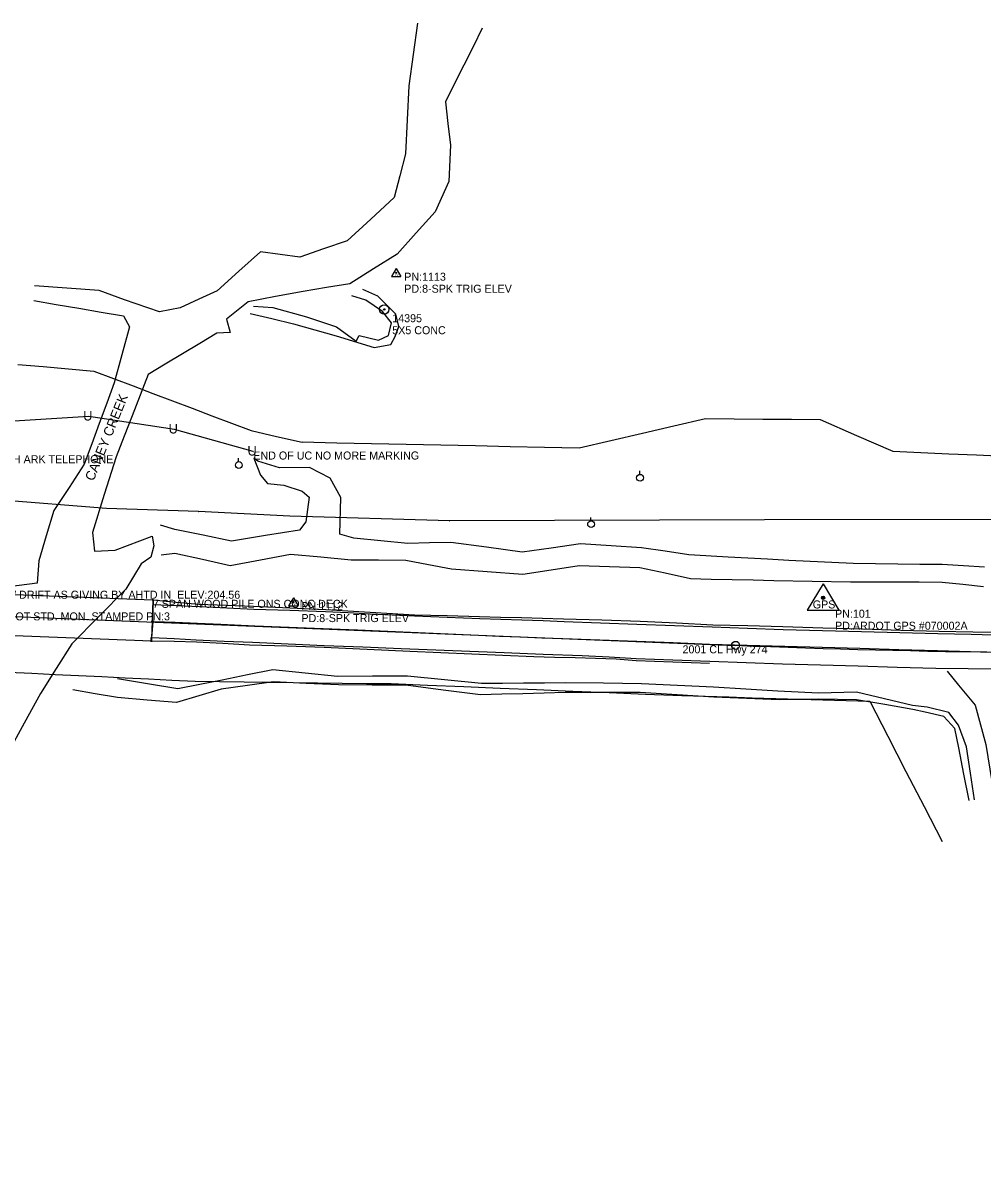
# Model space of a CAD drawing. Extents: x 1138803 to 1169983, y 1655906 to 1658226.
# Drawn here: x 1141577 to 1142177, y 1657286 to 1658006 of the extents above; entities that cross this region are included whole.
import ezdxf

# ---------------------------------------------------------------- set-up
doc = ezdxf.new("R2010")
doc.units = 0
for name, color, linetype in [('Default', 7, 'Continuous'), ('R_Annotation', 7, 'Continuous'), ('S_BRIDGE', 7, 'Continuous'), ('S_BRIDGE_ANNOT', 7, 'Continuous'), ('S_DITCHLINE', 7, 'Continuous'), ('S_EDGE_PAVEMENT', 7, 'Continuous'), ('S_EXISTING_ALIGNMENT', 7, 'Continuous'), ('S_EXISTING_ALIGNMENT_ANNOT', 7, 'Continuous'), ('S_FIBER_OPTIC_CABLE', 7, 'Continuous'), ('S_GRAVEL_ROAD', 7, 'Continuous'), ('S_HIST_HIGH_WATER_ANNOT', 7, 'Continuous'), ('S_IRON_PIN', 7, 'Continuous'), ('S_IRON_PIN_ANNOT', 7, 'Continuous'), ('S_MSC_PT_SYM', 7, 'Continuous'), ('S_PAVEMENT_CROWN', 7, 'Continuous'), ('S_PRIMARY_CTL', 7, 'Continuous'), ('S_PRIMARY_CTL_ANNOT', 7, 'Continuous'), ('S_SECONDARY_CTL', 7, 'Continuous'), ('S_SECONDARY_CTL_ANNOT', 7, 'Continuous'), ('S_SHOULDER', 7, 'Continuous'), ('S_STR_PT_SYM', 7, 'Continuous'), ('S_STREAM', 7, 'Continuous'), ('S_SURVEY_TEXT_ANNOT', 7, 'Continuous'), ('S_TREE', 7, 'Continuous'), ('S_UNDERGROUND_CABLE', 7, 'Continuous'), ('S_UTILITY_POLE', 7, 'Continuous'), ('S_UTILITY_POLE_ANNOT', 7, 'Continuous'), ('S_UTL_PT_SYM', 7, 'Continuous')]:
    doc.layers.add(name, color=color, linetype=linetype)

msp = doc.modelspace()

# ---------------------------------------------------------------- linework, layer by layer
at = {"layer": 'S_BRIDGE'}
for p, q in [((1141551.33, 1657650), (1141657.88, 1657645.9)), ((1141657.88, 1657645.9), (1141657.41, 1657632.31)), ((1141657.41, 1657632.31), (1141657.03, 1657621.9)), ((1141656.97, 1657620.11), (1141550.22, 1657624.21)), ((1141657.03, 1657621.9), (1141656.97, 1657620.63)), ((1141656.97, 1657620.63), (1141656.97, 1657620.11))]:
    msp.add_line(p, q, dxfattribs=at)
at = {"layer": 'S_DITCHLINE'}
for points in [[(1141718.73, 1657824.92), (1141732.27, 1657821.68), (1141745.82, 1657818.45), (1141759.11, 1657814.62), (1141772.41, 1657810.79), (1141796.27, 1657803.51), (1141806.65, 1657805.46), (1141809.29, 1657810.45), (1141811.59, 1657816.7), (1141809.83, 1657824.33), (1141798.52, 1657835.69), (1141789.15, 1657839.79)], [(1141720.76, 1657829.49), (1141732.83, 1657828.69), (1141753.89, 1657822.77), (1141772.79, 1657816.6), (1141785.06, 1657807.64), (1141786.87, 1657811), (1141798.88, 1657808.17), (1141805.12, 1657811.02), (1141807.13, 1657819.04), (1141801.49, 1657826), (1141791.13, 1657833.23), (1141782.24, 1657835.81)], [(1142177.83, 1657666.32), (1142164.58, 1657667.1), (1142151.33, 1657667.88), (1142137.42, 1657668.06), (1142123.51, 1657668.23), (1142109.6, 1657668.41), (1142095.69, 1657668.58), (1142082.27, 1657669.25), (1142068.85, 1657669.91), (1142055.43, 1657670.58), (1142042.01, 1657671.25), (1142017.45, 1657672.62), (1141992.89, 1657674), (1141978.17, 1657676.24), (1141963.44, 1657678.48), (1141944.33, 1657679.64), (1141925.21, 1657680.8), (1141906.97, 1657678.25), (1141888.73, 1657675.7), (1141866.46, 1657678.76), (1141844.19, 1657681.82), (1141830.78, 1657681.42), (1141817.37, 1657681.01), (1141800.49, 1657682.7), (1141783.6, 1657684.39), (1141774.69, 1657686.95), (1141775.46, 1657709.79), (1141768.71, 1657721.9), (1141755.78, 1657728.68), (1141736.99, 1657728.43), (1141723.49, 1657732.46), (1141720.94, 1657734.45), (1141725.21, 1657723.84), (1141729.47, 1657718.63), (1141739.76, 1657717.51), (1141751.29, 1657713.78), (1141755.64, 1657710.14), (1141753.6, 1657694.74), (1141749.5, 1657689.52), (1141728.24, 1657686.09), (1141706.98, 1657682.65), (1141689.27, 1657686.27), (1141671.56, 1657689.88), (1141662.65, 1657692.57)], [(1142177.17, 1657654.11), (1142164.22, 1657655.46), (1142151.28, 1657656.8), (1142136.97, 1657656.84), (1142122.67, 1657656.88), (1142108.36, 1657656.92), (1142094.06, 1657656.96), (1142070.1, 1657657.39), (1142046.13, 1657657.82), (1142033.08, 1657658.11), (1142020.02, 1657658.41), (1142006.97, 1657658.7), (1141993.91, 1657658.99), (1141978.12, 1657662.47), (1141962.33, 1657665.95), (1141943.39, 1657666.54), (1141924.45, 1657667.12), (1141906.79, 1657664.47), (1141889.13, 1657661.81), (1141866.8, 1657663.47), (1141844.48, 1657665.12), (1141830.26, 1657667.79), (1141816.05, 1657670.45), (1141798.95, 1657670.59), (1141781.86, 1657670.73), (1141762.92, 1657672.51), (1141743.97, 1657674.28), (1141725.14, 1657670.76), (1141706.31, 1657667.23), (1141689, 1657671.08), (1141671.69, 1657674.92), (1141663.08, 1657673.89)], [(1142171.5, 1657520.96), (1142168.99, 1657537.47), (1142166.49, 1657553.97), (1142161.57, 1657567.57), (1142155.52, 1657575.4), (1142141.81, 1657578.88), (1142132.82, 1657579.84), (1142115.26, 1657583.98), (1142097.69, 1657588.13), (1142073.89, 1657587.54), (1142061.28, 1657588.23), (1142048.67, 1657588.92), (1142028.51, 1657590.13), (1142008.34, 1657591.35), (1141985.83, 1657592.39), (1141963.32, 1657593.43), (1141939.61, 1657593.73), (1141915.9, 1657594.03), (1141902.76, 1657593.91), (1141889.62, 1657593.8), (1141876.47, 1657593.68), (1141863.33, 1657593.56), (1141840.19, 1657595.91), (1141817.05, 1657598.26), (1141795.21, 1657598.09), (1141773.37, 1657597.92), (1141753.13, 1657600.06), (1141732.88, 1657602.21), (1141717.09, 1657598.98), (1141701.29, 1657595.75), (1141687.36, 1657592.98), (1141673.42, 1657590.21), (1141654.59, 1657593.37), (1141635.77, 1657596.52)], [(1142168.11, 1657520.52), (1142164.89, 1657536.95), (1142161.67, 1657553.39), (1142159.15, 1657565.53), (1142152.34, 1657572.92), (1142140.61, 1657575.66), (1142132.92, 1657577.41), (1142115.38, 1657580.44), (1142097.83, 1657583.47), (1142074.06, 1657583.86), (1142049.31, 1657583.38), (1142028.92, 1657584.24), (1142008.53, 1657585.1), (1141985.56, 1657586.55), (1141962.6, 1657588), (1141939.13, 1657587.94), (1141915.67, 1657587.89), (1141902.43, 1657587.54), (1141889.19, 1657587.19), (1141875.95, 1657586.84), (1141862.71, 1657586.49), (1141839.36, 1657589.51), (1141816, 1657592.53), (1141795, 1657592.65), (1141773.99, 1657592.76), (1141753.67, 1657593.66), (1141733.35, 1657594.55), (1141716.97, 1657592.34), (1141700.6, 1657590.13), (1141686.66, 1657585.93), (1141672.71, 1657581.74), (1141654.25, 1657583.28), (1141635.79, 1657584.81), (1141621.8, 1657587.21), (1141607.82, 1657589.6)]]:
    msp.add_lwpolyline(points, dxfattribs=at)
at = {"layer": 'S_EDGE_PAVEMENT'}
for points in [[(1142187.85, 1657602.51), (1142167.59, 1657602.72), (1142147.34, 1657602.93), (1142123.11, 1657603.7), (1142098.88, 1657604.47), (1142075.14, 1657605.03), (1142051.4, 1657605.59), (1142028.68, 1657606.48), (1142005.96, 1657607.37), (1141982.99, 1657608.24), (1141960.03, 1657609.11), (1141943.17, 1657610.03), (1141926.3, 1657610.96), (1141901.89, 1657611.82), (1141877.47, 1657612.67), (1141861.4, 1657613.35), (1141845.34, 1657614.02), (1141829.27, 1657614.69), (1141813.21, 1657615.36), (1141789.14, 1657616.3), (1141765.07, 1657617.24), (1141742.58, 1657618.21), (1141720.09, 1657619.18), (1141702.56, 1657619.95), (1141685.04, 1657620.72), (1141671.17, 1657621.47), (1141657.31, 1657622.22), (1141658.08, 1657632.26), (1141658.07, 1657642.64)], [(1142190.31, 1657623.66), (1142169.41, 1657624.17), (1142148.51, 1657624.68), (1142124.74, 1657625.25), (1142100.96, 1657625.81), (1142076.39, 1657626.48), (1142051.81, 1657627.15), (1142029.68, 1657628.01), (1142007.54, 1657628.87), (1141984.02, 1657629.71), (1141960.5, 1657630.55), (1141937.75, 1657631.38), (1141915.01, 1657632.21), (1141901.81, 1657632.67), (1141888.61, 1657633.12), (1141875.4, 1657633.57), (1141862.2, 1657634.03), (1141841.78, 1657634.85), (1141821.37, 1657635.67), (1141807.51, 1657636.35), (1141793.65, 1657637.03), (1141779.78, 1657637.71), (1141765.92, 1657638.39), (1141743.52, 1657639.14), (1141721.11, 1657639.88), (1141704.1, 1657640.74), (1141687.08, 1657641.6), (1141672.61, 1657642.22), (1141658.14, 1657642.84)]]:
    msp.add_lwpolyline(points, dxfattribs=at)
at = {"layer": 'S_EXISTING_ALIGNMENT'}
msp.add_line((1140481.53, 1657679.14), (1142022.15, 1657617.46), dxfattribs=at)
msp.add_circle((1142022.15, 1657617.46), 2.5, dxfattribs=at)
msp.add_arc((1142252.26, 1663365.55), 5752.69, 267.707455, 274.678683, dxfattribs=at)
at = {"layer": 'S_FIBER_OPTIC_CABLE'}
for p, q in [((1141628.93, 1657703.02), (1141522.77, 1657711.39)), ((1141686.36, 1657701.07), (1141628.93, 1657703.02)), ((1141743.49, 1657698.2), (1141686.36, 1657701.07)), ((1141843.42, 1657695.23), (1141743.49, 1657698.2)), ((1142040.24, 1657695.96), (1141843.42, 1657695.23)), ((1142205.85, 1657696.12), (1142040.24, 1657695.96))]:
    msp.add_line(p, q, dxfattribs=at)
at = {"layer": 'S_GRAVEL_ROAD'}
msp.add_lwpolyline([(1142154.33, 1657601.26), (1142161.44, 1657592.63), (1142171.83, 1657580.17), (1142175.18, 1657567.86), (1142178.54, 1657555.56), (1142182.38, 1657532.32), (1142183.56, 1657516.44), (1142184.74, 1657500.56), (1142185.59, 1657476.1), (1142186.43, 1657451.65), (1142187.52, 1657429.02), (1142188.61, 1657406.39), (1142189.59, 1657381.64), (1142190.57, 1657356.89), (1142191.64, 1657340.42), (1142192.7, 1657323.94), (1142193.66, 1657304.9), (1142194.61, 1657285.86)], dxfattribs=at)
at = {"layer": 'S_IRON_PIN'}
for radius in [2.91, 0.411, 0.262, 0.212, 0.145, 0.0822, 0.0581]:
    msp.add_circle((1141802.55, 1657827.38), radius, dxfattribs=at)
at = {"layer": 'S_MSC_PT_SYM'}
msp.add_lwpolyline([(1141720.7, 1657738.58), (1141720.7, 1657738.63), (1141720.7, 1657738.58), (1141720.65, 1657738.58), (1141720.7, 1657738.58), (1141720.7, 1657738.53), (1141720.7, 1657738.58), (1141720.75, 1657738.58)], dxfattribs=at)
at = {"layer": 'S_PAVEMENT_CROWN'}
msp.add_lwpolyline([(1142189.52, 1657612.97), (1142168.97, 1657613.5), (1142148.43, 1657614.03), (1142124.12, 1657614.72), (1142099.8, 1657615.41), (1142076.36, 1657616.05), (1142052.91, 1657616.7), (1142029.37, 1657617.39), (1142005.84, 1657618.08), (1141983.08, 1657619), (1141960.33, 1657619.91), (1141937.21, 1657620.71), (1141914.09, 1657621.5), (1141900.95, 1657622.02), (1141887.8, 1657622.53), (1141874.66, 1657623.05), (1141861.52, 1657623.57), (1141842.59, 1657624.42), (1141823.67, 1657625.27), (1141804.75, 1657626.11), (1141785.82, 1657626.96), (1141764.46, 1657627.82), (1141743.09, 1657628.67), (1141721.72, 1657629.53), (1141700.36, 1657630.38), (1141685.79, 1657631.1), (1141671.95, 1657631.68), (1141658.51, 1657632.24)], dxfattribs=at)
at = {"layer": 'S_PRIMARY_CTL'}
for p, q in [((1142076.83, 1657655.92), (1142066.8, 1657639.41)), ((1142076.83, 1657655.92), (1142086.66, 1657639.41)), ((1142066.8, 1657639.41), (1142086.66, 1657639.41))]:
    msp.add_line(p, q, dxfattribs=at)
for radius in [1.04, 0.609, 0.344]:
    msp.add_circle((1142076.83, 1657647.22), radius, dxfattribs=at)
at = {"layer": 'S_SECONDARY_CTL'}
for p, q in [((1141810.06, 1657852.93), (1141807.05, 1657847.97)), ((1141810.06, 1657852.93), (1141813.01, 1657847.97)), ((1141807.05, 1657847.97), (1141813.01, 1657847.97)), ((1141745.76, 1657647.09), (1141742.75, 1657642.14)), ((1141745.76, 1657647.09), (1141748.7, 1657642.14)), ((1141742.75, 1657642.14), (1141748.7, 1657642.14))]:
    msp.add_line(p, q, dxfattribs=at)
for centre, radius in [((1141810.06, 1657850.32), 0.311), ((1141810.06, 1657850.32), 0.183), ((1141810.06, 1657850.32), 0.103), ((1141745.76, 1657644.48), 0.311), ((1141745.76, 1657644.48), 0.183), ((1141745.76, 1657644.48), 0.103)]:
    msp.add_circle(centre, radius, dxfattribs=at)
at = {"layer": 'S_SHOULDER'}
for points in [[(1142191.33, 1657625.49), (1142170.42, 1657625.78), (1142149.51, 1657626.06), (1142125.5, 1657626.83), (1142101.49, 1657627.61), (1142076.6, 1657628.28), (1142051.71, 1657628.96), (1142029.83, 1657629.55), (1142007.95, 1657630.14), (1141985.22, 1657631.26), (1141962.48, 1657632.38), (1141938.57, 1657633.11), (1141914.67, 1657633.84), (1141901.51, 1657634.21), (1141888.35, 1657634.57), (1141875.19, 1657634.93), (1141862.04, 1657635.3), (1141841.79, 1657635.84), (1141821.55, 1657636.37), (1141807.66, 1657637.19), (1141793.77, 1657638.02), (1141779.88, 1657638.84), (1141765.99, 1657639.66), (1141743.44, 1657640.71), (1141720.89, 1657641.76), (1141703.81, 1657642.36), (1141686.73, 1657642.97), (1141672.46, 1657644.32), (1141658.18, 1657645.67), (1141658.17, 1657644.17), (1141658.02, 1657643.09)], [(1142005.8, 1657606.21), (1141982.9, 1657606.96), (1141959.99, 1657607.72), (1141947.52, 1657608.87), (1141934.66, 1657609.23), (1141921.79, 1657609.58), (1141908.92, 1657609.94), (1141896.06, 1657610.3), (1141876.7, 1657611.15), (1141857.34, 1657612), (1141837.99, 1657612.84), (1141818.63, 1657613.69), (1141805.21, 1657614.32), (1141791.78, 1657614.95), (1141778.36, 1657615.58), (1141764.94, 1657616.21), (1141741.61, 1657616.93), (1141718.29, 1657617.66), (1141701.7, 1657618.53), (1141685.12, 1657619.4), (1141671.16, 1657619.76), (1141657.2, 1657620.12), (1141657.22, 1657621.67)]]:
    msp.add_lwpolyline(points, dxfattribs=at)
at = {"layer": 'S_STR_PT_SYM'}
for points in [[(1141657.88, 1657645.9), (1141657.88, 1657646.4), (1141657.88, 1657645.9), (1141657.38, 1657645.9), (1141657.88, 1657645.9), (1141657.88, 1657645.4), (1141657.88, 1657645.9), (1141658.38, 1657645.9)], [(1141657.41, 1657632.31), (1141657.41, 1657632.81), (1141657.41, 1657632.31), (1141656.91, 1657632.31), (1141657.41, 1657632.31), (1141657.41, 1657631.81), (1141657.41, 1657632.31), (1141657.91, 1657632.31)], [(1141657.03, 1657621.9), (1141657.03, 1657622.4), (1141657.03, 1657621.9), (1141656.53, 1657621.9), (1141657.03, 1657621.9), (1141657.03, 1657621.4), (1141657.03, 1657621.9), (1141657.53, 1657621.9)], [(1141656.97, 1657620.63), (1141656.97, 1657621.13), (1141656.97, 1657620.63), (1141656.47, 1657620.63), (1141656.97, 1657620.63), (1141656.97, 1657620.13), (1141656.97, 1657620.63), (1141657.47, 1657620.63)], [(1141656.97, 1657620.11), (1141656.97, 1657620.61), (1141656.97, 1657620.11), (1141656.47, 1657620.11), (1141656.97, 1657620.11), (1141656.97, 1657619.61), (1141656.97, 1657620.11), (1141657.47, 1657620.11)]]:
    msp.add_lwpolyline(points, dxfattribs=at)
at = {"layer": 'S_STREAM'}
for points in [[(1141823.43, 1658006.35), (1141820.7, 1657986.77), (1141817.96, 1657967.19), (1141816.94, 1657945.93), (1141815.92, 1657924.67), (1141812.36, 1657910.96), (1141808.79, 1657897.25), (1141794.08, 1657883.78), (1141779.37, 1657870.31), (1141764.61, 1657865.15), (1141749.84, 1657859.99), (1141725.09, 1657863.34), (1141711.63, 1657851.19), (1141698.16, 1657839.04), (1141686.61, 1657833.75), (1141675.05, 1657828.46), (1141662.14, 1657825.83), (1141640.15, 1657833.45), (1141624.44, 1657839.13), (1141604.14, 1657840.68), (1141583.85, 1657842.22)], [(1141863.81, 1658003.08), (1141858.06, 1657991.59), (1141852.31, 1657980.1), (1141846.56, 1657968.61), (1141840.81, 1657957.12), (1141842.36, 1657943.61), (1141843.92, 1657930.11), (1141842.88, 1657907.28), (1141834.35, 1657888.46), (1141822.5, 1657875.17), (1141810.66, 1657861.88), (1141795.86, 1657852.66), (1141781.06, 1657843.45), (1141766.45, 1657841.03), (1141751.85, 1657838.61), (1141734.62, 1657835.42), (1141717.39, 1657832.23), (1141703.97, 1657821.28), (1141706.31, 1657812.99), (1141697.91, 1657812.55), (1141687.17, 1657806.07), (1141676.43, 1657799.59), (1141665.7, 1657793.12), (1141654.96, 1657786.64), (1141649.94, 1657773.8), (1141644.92, 1657760.96), (1141639.9, 1657748.12), (1141634.89, 1657735.28), (1141627.48, 1657711.65), (1141620.08, 1657688.03), (1141621.41, 1657676.38), (1141634.36, 1657676.88), (1141657.49, 1657685.6), (1141658.55, 1657679.56), (1141656.7, 1657672.58), (1141650.65, 1657668.33), (1141641.08, 1657652.46), (1141624.21, 1657635.48), (1141607.35, 1657618.5), (1141597.53, 1657602.95), (1141587.71, 1657587.4), (1141577.5, 1657568.72), (1141567.3, 1657550.04)], [(1141583.57, 1657832.92), (1141597.56, 1657830.51), (1141611.54, 1657828.1), (1141625.52, 1657825.7), (1141639.5, 1657823.29), (1141643.36, 1657816.42), (1141638.54, 1657799.02), (1141633.73, 1657781.61), (1141629.05, 1657768.88), (1141624.38, 1657756.14), (1141619.71, 1657743.4), (1141615.04, 1657730.67), (1141605.49, 1657716.14), (1141595.93, 1657701.62), (1141591.24, 1657685.93), (1141586.55, 1657670.23), (1141585.68, 1657656.36), (1141567.92, 1657654.08)]]:
    msp.add_lwpolyline(points, dxfattribs=at)
at = {"layer": 'S_TREE'}
for points in [[(1141573.53, 1657793.03), (1141589.37, 1657791.65), (1141605.2, 1657790.26), (1141621.03, 1657788.87), (1141633.33, 1657784.22), (1141645.62, 1657779.56), (1141657.92, 1657774.91), (1141670.21, 1657770.25), (1141682.5, 1657765.6), (1141694.8, 1657760.94), (1141707.09, 1657756.29), (1141719.39, 1657751.63), (1141735.27, 1657748.06), (1141751.16, 1657744.49), (1141751.16, 1657744.55), (1141772.82, 1657744.09), (1141794.49, 1657743.64), (1141816.15, 1657743.18), (1141837.82, 1657742.73), (1141859.48, 1657742.28), (1141881.15, 1657741.82), (1141902.81, 1657741.37), (1141924.48, 1657740.91), (1141944.19, 1657745.48), (1141963.9, 1657750.04), (1141983.61, 1657754.6), (1142003.32, 1657759.17), (1142021.23, 1657759.02), (1142039.14, 1657758.88), (1142057.05, 1657758.73), (1142074.96, 1657758.58), (1142097.74, 1657748.69), (1142120.53, 1657738.79), (1142137.95, 1657738.01), (1142155.37, 1657737.24), (1142172.79, 1657736.46), (1142190.21, 1657735.68)], [(1141567.6, 1657600.7), (1141582.19, 1657600), (1141596.79, 1657599.29), (1141611.38, 1657598.59), (1141625.97, 1657597.89), (1141640.56, 1657597.18), (1141655.16, 1657596.48), (1141669.75, 1657595.78), (1141684.34, 1657595.07), (1141699.65, 1657594.88), (1141714.97, 1657594.68), (1141730.28, 1657594.49), (1141745.59, 1657594.29), (1141760.9, 1657594.09), (1141776.22, 1657593.9), (1141791.53, 1657593.7), (1141806.84, 1657593.51), (1141829.55, 1657592.58), (1141852.26, 1657591.65), (1141874.96, 1657590.73), (1141897.67, 1657589.8), (1141920.38, 1657588.88), (1141943.09, 1657587.95), (1141965.8, 1657587.02), (1141988.5, 1657586.1), (1142003.19, 1657585.65), (1142017.89, 1657585.2), (1142032.58, 1657584.75), (1142047.27, 1657584.31), (1142061.96, 1657583.86), (1142076.65, 1657583.41), (1142091.34, 1657582.97), (1142106.03, 1657582.52), (1142117.35, 1657560.61), (1142128.66, 1657538.7), (1142139.98, 1657516.79), (1142151.3, 1657494.89)]]:
    msp.add_lwpolyline(points, dxfattribs=at)
at = {"layer": 'S_UNDERGROUND_CABLE'}
for p, q in [((1141617.98, 1657760.5), (1141564.59, 1657757.22)), ((1141671.4, 1657752.41), (1141617.98, 1657760.5)), ((1141720.69, 1657738.62), (1141671.4, 1657752.41))]:
    msp.add_line(p, q, dxfattribs=at)
at = {"layer": 'S_UTILITY_POLE'}
for p, q in [((1141711.52, 1657732.28), (1141711.52, 1657734.39)), ((1141962.33, 1657724.33), (1141962.33, 1657726.44)), ((1141931.71, 1657695.33), (1141931.71, 1657697.44))]:
    msp.add_line(p, q, dxfattribs=at)
for centre in [(1141711.65, 1657730.14), (1141962.45, 1657722.19), (1141931.83, 1657693.19)]:
    msp.add_circle(centre, 2.13, dxfattribs=at)
at = {"layer": 'S_UTL_PT_SYM'}
for points in [[(1141628.93, 1657703.02), (1141628.93, 1657703.07), (1141628.93, 1657703.02), (1141628.88, 1657703.02), (1141628.93, 1657703.02), (1141628.93, 1657702.97), (1141628.93, 1657703.02), (1141628.98, 1657703.02)], [(1141686.36, 1657701.07), (1141686.36, 1657701.12), (1141686.36, 1657701.07), (1141686.31, 1657701.07), (1141686.36, 1657701.07), (1141686.36, 1657701.02), (1141686.36, 1657701.07), (1141686.41, 1657701.07)], [(1141743.49, 1657698.2), (1141743.49, 1657698.25), (1141743.49, 1657698.2), (1141743.44, 1657698.2), (1141743.49, 1657698.2), (1141743.49, 1657698.15), (1141743.49, 1657698.2), (1141743.54, 1657698.2)], [(1141843.42, 1657695.23), (1141843.42, 1657695.28), (1141843.42, 1657695.23), (1141843.37, 1657695.23), (1141843.42, 1657695.23), (1141843.42, 1657695.18), (1141843.42, 1657695.23), (1141843.47, 1657695.23)], [(1142040.24, 1657695.96), (1142040.24, 1657696.01), (1142040.24, 1657695.96), (1142040.19, 1657695.96), (1142040.24, 1657695.96), (1142040.24, 1657695.91), (1142040.24, 1657695.96), (1142040.29, 1657695.96)]]:
    msp.add_lwpolyline(points, dxfattribs=at)

# ---------------------------------------------------------------- texts
at = {"layer": 'Default'}
for p in [(1141614.35, 1657757.96), (1141667.77, 1657749.86), (1141717.06, 1657736.07)]:
    msp.add_text('U', height=6, rotation=360, dxfattribs=at).set_placement(p)
at = {"layer": 'R_Annotation'}
msp.add_text('CANEY CREEK', height=6, rotation=67.83806, dxfattribs=at).set_placement((1141620.82, 1657719.73))
at = {"layer": 'S_BRIDGE_ANNOT'}
msp.add_text('7 SPAN WOOD PILE ONS CONC DECK', height=5, dxfattribs=at).set_placement((1141657.88, 1657640.9))
at = {"layer": 'S_EXISTING_ALIGNMENT_ANNOT'}
msp.add_text('2001 CL Hwy 274', height=5, dxfattribs=at).set_placement((1141988.98, 1657612.46))
at = {"layer": 'S_HIST_HIGH_WATER_ANNOT'}
msp.add_text('HHW DRIFT AS GIVING BY AHTD IN  ELEV:204.56', height=5, dxfattribs=at).set_placement((1141556.45, 1657646.6))
at = {"layer": 'S_IRON_PIN_ANNOT'}
for s, p in [('14395', (1141807.55, 1657819.38)), ('5X5 CONC', (1141807.55, 1657811.88))]:
    msp.add_text(s, height=5, dxfattribs=at).set_placement(p)
at = {"layer": 'S_PRIMARY_CTL'}
msp.add_text('GPS', height=5, rotation=360, dxfattribs=at).set_placement((1142070.4, 1657640.52))
at = {"layer": 'S_PRIMARY_CTL_ANNOT'}
for s, p in [('PD:ARDOT STD. MON. STAMPED PN:3', (1141546.75, 1657633.06)), ('PN:101', (1142084.33, 1657634.72)), ('PD:ARDOT GPS #070002A', (1142084.33, 1657627.22))]:
    msp.add_text(s, height=5, dxfattribs=at).set_placement(p)
at = {"layer": 'S_SECONDARY_CTL'}
for p in [(1141808.86, 1657848.3), (1141744.55, 1657642.47)]:
    msp.add_text('TV', height=1.5, rotation=360, dxfattribs=at).set_placement(p)
at = {"layer": 'S_SECONDARY_CTL_ANNOT'}
for s, p in [('PN:1113', (1141815.06, 1657845.32)), ('PD:8-SPK TRIG ELEV', (1141815.06, 1657837.82)), ('PN:1112', (1141750.76, 1657639.48)), ('PD:8-SPK TRIG ELEV', (1141750.76, 1657631.98))]:
    msp.add_text(s, height=5, dxfattribs=at).set_placement(p)
at = {"layer": 'S_SURVEY_TEXT_ANNOT'}
msp.add_text('END OF UC NO MORE MARKING', height=5, dxfattribs=at).set_placement((1141720.7, 1657733.58))
at = {"layer": 'S_UTILITY_POLE_ANNOT'}
msp.add_text('SOUTH ARK TELEPHONE', height=5, dxfattribs=at).set_placement((1141551.85, 1657731.28))

doc.saveas('drawing.dxf')
